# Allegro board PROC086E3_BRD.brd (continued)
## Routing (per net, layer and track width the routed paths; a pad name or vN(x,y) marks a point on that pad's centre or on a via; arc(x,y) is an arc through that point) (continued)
OV_VIN_DATA1: length 66.5
  TOP w0.178: v1(57.54,175.21) 57.34,175.01 U6.35
  L03_SIG1 w0.107: J3.25 9.2,192.43 9.2,190.57 10.44,189.34 11.53,189.34 13.51,187.36 31.65,187.36 32.49,186.52 32.49,185.76 32.58,185.67 33.23,185.67 33.32,185.58 33.32,185.44 33.23,185.35 32.58,185.35 32.49,185.26 32.49,177.38 33.96,175.9 56.85,175.9 v1(57.54,175.21)
OV_VIN_DATA2: length 66.6
  TOP w0.178: U6.33 58.14,175.62 v1(58.74,176.22)
  L03_SIG1 w0.107: J3.24 15.53,188.43 32.66,188.43 37.29,183.8 37.29,179 39.27,177.02 39.57,177.02 39.66,177.11 39.66,177.69 39.75,177.78 39.89,177.78 39.98,177.69 39.98,177.11 40.07,177.02 40.21,177.02 40.3,177.11 40.3,177.69 40.39,177.78 40.53,177.78 40.62,177.69 40.62,177.11 40.71,177.02 40.85,177.02 40.94,177.11 40.94,177.69 41.03,177.78 41.17,177.78 41.26,177.69 41.26,177.11 41.35,177.02 41.49,177.02 41.58,177.11 41.58,177.69 41.67,177.78 41.81,177.78 41.9,177.69 41.9,177.11 41.99,177.02 42.13,177.02 42.22,177.11 42.22,177.69 42.31,177.78 42.45,177.78 42.54,177.69 42.54,177.11 42.63,177.02 42.77,177.02 42.86,177.11 42.86,177.69 42.95,177.78 43.09,177.78 43.18,177.69 43.18,177.11 43.27,177.02 43.41,177.02 43.5,177.11 43.5,177.69 43.59,177.78 43.73,177.78 43.82,177.69 43.82,177.11 43.91,177.02 57.95,177.02 v1(58.74,176.22)
OV_VIN_DATA3: length 66.6
  TOP w0.178: v1(58.74,175.21) 58.54,175.01 U6.32
  L03_SIG1 w0.107: J3.23 11.74,192.43 11.74,190.42 14.07,188.1 32.49,188.1 35.2,185.38 35.2,177.07 35.59,176.69 36.16,176.69 36.26,176.78 36.26,177.21 36.35,177.3 36.48,177.3 36.58,177.21 36.58,176.78 36.67,176.69 36.8,176.69 36.9,176.78 36.9,177.21 36.99,177.3 37.12,177.3 37.22,177.21 37.22,176.78 37.31,176.69 37.44,176.69 37.54,176.78 37.54,177.21 37.63,177.3 37.76,177.3 37.86,177.21 37.86,176.78 37.95,176.69 57.84,176.69 58.22,176.31 58.22,175.73 v1(58.74,175.21)
OV_VIN_DATA4: length 66.5
  TOP w0.178: v1(59.94,176.22) 59.34,175.62 U6.30
  L03_SIG1 w0.107: J3.2 40.84,187.36 46.25,181.95 46.6,181.95 46.69,181.85 46.69,181.25 46.79,181.16 46.92,181.16 47.01,181.25 47.01,181.85 47.11,181.95 47.24,181.95 47.33,181.85 47.33,181.25 47.43,181.16 47.56,181.16 47.65,181.25 47.65,181.85 47.75,181.95 47.88,181.95 47.97,181.85 47.97,181.25 48.07,181.16 48.2,181.16 48.29,181.25 48.29,181.85 48.39,181.95 48.52,181.95 48.61,181.85 48.61,181.25 48.71,181.16 48.84,181.16 48.93,181.25 48.93,181.85 49.03,181.95 49.16,181.95 49.25,181.85 49.25,181.25 49.35,181.16 49.48,181.16 49.57,181.25 49.57,181.85 49.67,181.95 49.8,181.95 49.89,181.85 49.89,181.25 49.99,181.16 50.12,181.16 50.21,181.25 50.21,181.85 50.31,181.95 50.44,181.95 50.53,181.85 50.53,181.25 50.63,181.16 50.76,181.16 50.85,181.25 50.85,181.85 50.95,181.95 51.08,181.95 51.17,181.85 51.17,181.25 51.27,181.16 51.4,181.16 51.49,181.25 51.49,181.85 51.59,181.95 52.36,181.95 52.45,181.85 52.45,181.25 52.55,181.16 52.68,181.16 52.77,181.25 52.77,181.85 52.87,181.95 53,181.95 53.09,181.85 53.09,181.25 53.19,181.16 53.32,181.16 53.41,181.25 53.41,181.85 53.51,181.95 53.64,181.95 53.73,181.85 53.73,181.25 53.83,181.16 53.96,181.16 54.05,181.25 54.05,181.85 54.15,181.95 54.28,181.95 54.37,181.85 54.37,181.25 54.47,181.16 54.6,181.16 54.69,181.25 54.69,181.85 54.79,181.95 54.92,181.95 55.01,181.85 55.01,181.25 55.11,181.16 55.24,181.16 55.33,181.25 55.33,181.85 55.43,181.95 55.56,181.95 55.65,181.85 55.65,181.25 55.75,181.16 55.88,181.16 55.97,181.25 55.97,181.85 56.07,181.95 56.2,181.95 56.29,181.85 56.29,181.25 56.39,181.16 56.52,181.16 56.61,181.25 56.61,181.85 56.71,181.95 56.84,181.95 56.93,181.85 56.93,181.25 57.03,181.16 57.16,181.16 57.25,181.25 57.25,181.85 57.35,181.95 57.48,181.95 57.57,181.85 57.57,181.25 57.67,181.16 57.8,181.16 57.89,181.25 57.89,181.85 57.99,181.95 58.12,181.95 58.21,181.85 58.21,181.25 58.31,181.16 58.44,181.16 58.53,181.25 58.53,181.85 58.63,181.95 58.76,181.95 58.85,181.85 58.85,181.25 58.95,181.16 59.08,181.16 59.17,181.25 59.17,181.85 59.27,181.95 59.4,181.95 59.49,181.85 59.49,181.25 59.59,181.16 59.72,181.16 59.81,181.25 59.81,181.85 59.91,181.95 60.04,181.95 60.13,181.85 60.13,181.25 60.23,181.16 60.36,181.16 60.45,181.25 60.45,181.85 60.55,181.95 60.83,181.95 61.06,181.72 61.06,181.5 61.16,181.41 61.4,181.41 61.49,181.31 61.49,181.18 61.4,181.09 61.16,181.09 61.06,180.99 61.06,180.86 61.16,180.77 61.4,180.77 61.49,180.67 61.49,180.54 61.4,180.45 61.16,180.45 61.06,180.35 61.06,178.6 61.6,178.05 61.6,176.03 61.33,175.76 60.4,175.76 v1(59.94,176.22)
OV_VIN_DATA5: length 66.5
  TOP w0.178: U6.29 59.74,175.01 v1(59.94,175.21)
  L03_SIG1 w0.107: v1(59.94,175.21) 61.64,175.21 62.08,175.65 62.08,182 61.72,182.35 60.42,182.35 60.32,182.45 60.32,183.02 60.23,183.12 60.1,183.12 60,183.02 60,182.45 59.91,182.35 59.78,182.35 59.68,182.45 59.68,183.02 59.59,183.12 59.46,183.12 59.36,183.02 59.36,182.45 59.27,182.35 59.14,182.35 59.04,182.45 59.04,183.02 58.95,183.12 58.81,183.12 58.72,183.02 58.72,182.45 58.63,182.35 58.49,182.35 58.4,182.45 58.4,183.02 58.31,183.12 58.17,183.12 58.08,183.02 58.08,182.45 57.99,182.35 57.85,182.35 57.76,182.45 57.76,183.02 57.67,183.12 57.53,183.12 57.44,183.02 57.44,182.45 57.35,182.35 57.21,182.35 57.12,182.45 57.12,183.02 57.03,183.12 56.89,183.12 56.8,183.02 56.8,182.45 56.71,182.35 56.57,182.35 56.48,182.45 56.48,183.02 56.39,183.12 56.25,183.12 56.16,183.02 56.16,182.45 56.07,182.35 55.93,182.35 55.84,182.45 55.84,183.02 55.75,183.12 55.61,183.12 55.52,183.02 55.52,182.45 55.43,182.35 55.29,182.35 55.2,182.45 55.2,183.02 55.11,183.12 54.97,183.12 54.88,183.02 54.88,182.45 54.79,182.35 54.65,182.35 54.56,182.45 54.56,183.02 54.47,183.12 54.33,183.12 54.24,183.02 54.24,182.45 54.15,182.35 54.01,182.35 53.92,182.45 53.92,183.02 53.83,183.12 53.69,183.12 53.6,183.02 53.6,182.45 53.51,182.35 53.37,182.35 53.28,182.45 53.28,183.02 53.19,183.12 53.05,183.12 52.96,183.02 52.96,182.45 52.87,182.35 52.73,182.35 52.64,182.45 52.64,183.02 52.55,183.12 52.41,183.12 52.32,183.02 52.32,182.45 52.23,182.35 52.09,182.35 52,182.45 52,183.02 51.91,183.12 51.77,183.12 51.68,183.02 51.68,182.45 51.59,182.35 51.45,182.35 51.36,182.45 51.36,183.02 51.27,183.12 51.13,183.12 51.04,183.02 51.04,182.45 50.95,182.35 50.81,182.35 50.72,182.45 50.72,183.02 50.63,183.12 50.49,183.12 50.4,183.02 50.4,182.45 50.31,182.35 50.17,182.35 50.08,182.45 50.08,183.02 49.99,183.12 49.85,183.12 49.76,183.02 49.76,182.45 49.67,182.35 49.53,182.35 49.44,182.45 49.44,183.02 49.35,183.12 49.21,183.12 49.12,183.02 49.12,182.45 49.03,182.35 48.81,182.35 48.71,182.45 48.71,182.95 48.62,183.04 48.49,183.04 48.39,182.95 48.39,182.45 48.3,182.35 48.17,182.35 48.07,182.45 48.07,182.95 47.98,183.04 47.85,183.04 47.75,182.95 47.75,182.45 47.66,182.35 47.53,182.35 47.43,182.45 47.43,182.95 47.34,183.04 47.21,183.04 47.11,182.95 47.11,182.45 47.02,182.35 46.3,182.35 43.59,185.07 43.59,190.85 J3.1
OV_VIN_DATA6: length 66.5
  TOP w0.178: v1(61.14,176.22) 60.54,175.62 U6.27
  L03_SIG1 w0.107: v1(61.14,176.22) 60.1,177.27 60.1,180.62 59.99,180.73 59.59,180.73 59.48,180.62 59.48,179.88 59.39,179.79 59.26,179.79 59.16,179.88 59.16,180.64 59.07,180.73 58.94,180.73 58.84,180.64 58.84,179.88 58.75,179.79 58.62,179.79 58.52,179.88 58.52,180.64 58.43,180.73 58.3,180.73 58.2,180.64 58.2,179.88 58.11,179.79 57.98,179.79 57.88,179.88 57.88,180.64 57.79,180.73 56.54,180.73 56.44,180.64 56.44,179.1 56.35,179 56.22,179 56.12,179.1 56.12,180.64 56.03,180.73 53.9,180.73 53.81,180.64 53.81,179.17 53.71,179.08 53.58,179.08 53.49,179.17 53.49,180.64 53.39,180.73 53.26,180.73 53.17,180.64 53.17,179.17 53.07,179.08 52.94,179.08 52.85,179.17 52.85,180.64 52.75,180.73 52.62,180.73 52.53,180.64 52.53,179.17 52.43,179.08 52.3,179.08 52.21,179.17 52.21,180.64 52.11,180.73 51.98,180.73 51.89,180.64 51.89,179.17 51.79,179.08 51.66,179.08 51.57,179.17 51.57,180.64 51.47,180.73 51.34,180.73 51.25,180.64 51.25,179.17 51.15,179.08 51.02,179.08 50.93,179.17 50.93,180.64 50.83,180.73 50.7,180.73 50.61,180.64 50.61,179.17 50.51,179.08 50.38,179.08 50.29,179.17 50.29,180.64 50.19,180.73 48.96,180.73 48.86,180.64 48.86,180.27 48.77,180.17 48.64,180.17 48.54,180.27 48.54,180.64 48.45,180.73 48.32,180.73 48.22,180.64 48.22,180.27 48.13,180.17 48,180.17 47.9,180.27 47.9,180.64 47.81,180.73 47.68,180.73 47.58,180.64 47.58,180.27 47.49,180.17 47.36,180.17 47.26,180.27 47.26,180.64 47.17,180.73 47.04,180.73 46.94,180.64 46.94,180.27 46.85,180.17 46.72,180.17 46.62,180.27 46.62,180.64 46.53,180.73 46.4,180.73 46.3,180.64 46.3,180.27 46.21,180.17 46.08,180.17 45.98,180.27 45.98,180.64 45.89,180.73 45.67,180.73 45.42,180.98 45.42,182.34 38.3,189.45 J3.4
OV_VIN_DATA7: length 66.5
  TOP w0.178: U6.26 v1(60.94,172.69)
  L03_SIG1 w0.107: v1(60.94,172.69) 59.28,174.35 59.28,176.33 58.27,177.35 46.2,177.35 44.37,179.18 43.54,179.18 43.44,179.27 43.44,180.66 43.35,180.75 43.22,180.75 43.12,180.66 43.12,179.27 43.03,179.18 42.9,179.18 42.8,179.27 42.8,180.66 42.71,180.75 42.58,180.75 42.48,180.66 42.48,179.27 42.39,179.18 42.26,179.18 42.16,179.27 42.16,180.66 42.07,180.75 41.94,180.75 41.84,180.66 41.84,179.27 41.75,179.18 41.62,179.18 41.52,179.27 41.52,180.66 41.43,180.75 41.3,180.75 41.2,180.66 41.2,179.27 41.11,179.18 40.98,179.18 40.88,179.27 40.88,180.66 40.79,180.75 40.66,180.75 40.56,180.66 40.56,179.27 40.47,179.18 40.34,179.18 40.24,179.27 40.24,180.66 40.15,180.75 40.02,180.75 39.92,180.66 39.92,179.27 39.83,179.18 39.7,179.18 39.6,179.27 39.6,180.66 39.51,180.75 39.38,180.75 39.28,180.66 39.28,179.27 39.19,179.18 39.06,179.18 38.96,179.27 38.96,180.66 38.87,180.75 38.74,180.75 38.64,180.66 38.64,179.27 38.55,179.18 38.25,179.18 37.85,179.59 37.85,184.03 37.14,184.73 37.14,192.3 38.3,193.45 J3.3
OV_VIN_DATA8: length 66.5
  TOP w0.178: J3.6 35.76,189.85 35.53,189.62 32.31,189.62 32.13,189.44 32.13,188.6 32.36,188.37 32.68,188.37 32.83,188.53 32.83,188.9 32.99,189.06 33.21,189.06 33.37,188.9 33.37,188.53 33.52,188.37 33.74,188.37 33.9,188.53 33.9,188.9 34.06,189.06 34.28,189.06 34.43,188.9 34.43,188.53 34.59,188.37 34.81,188.37 34.97,188.53 34.97,188.9 35.12,189.06 35.34,189.06 35.5,188.9 35.5,188.53 35.66,188.37 35.88,188.37 36.03,188.53 36.03,188.9 36.19,189.06 36.41,189.06 36.57,188.9 36.57,188.53 36.72,188.37 36.94,188.37 37.1,188.53 37.1,188.9 37.26,189.06 37.48,189.06 37.63,188.9 37.63,188.53 37.79,188.37 38.01,188.37 38.17,188.53 38.17,188.9 38.32,189.06 38.54,189.06 38.7,188.9 38.7,188.53 38.86,188.37 39.08,188.37 39.23,188.53 39.23,188.9 39.39,189.06 39.61,189.06 39.77,188.9 39.77,188.53 39.92,188.37 40.14,188.37 40.3,188.53 40.3,188.9 40.46,189.06 40.68,189.06 40.83,188.9 40.83,188.53 40.99,188.37 41.59,188.37 41.75,188.53 41.75,188.9 41.9,189.06 42.75,189.06 43.28,188.53 55.55,188.53 57.21,186.86 58.61,186.86 58.76,186.71 58.76,186.35 58.92,186.19 59.14,186.19 59.3,186.35 59.3,186.71 59.45,186.86 59.68,186.86 59.83,186.71 59.83,186.35 59.99,186.19 60.21,186.19 60.36,186.35 60.36,186.71 60.52,186.86 66.23,186.86 66.6,186.5 66.6,183.96 66.78,183.78 68.26,183.78 68.61,183.43 68.61,175.67 68.25,175.32 U7.36
OV_VIN_DATA9: length 66.5
  TOP w0.178: U7.35 68.65,175.08 69.04,175.47 69.04,183.85 68.15,184.74 68.15,186.22 67.12,187.24 62.95,187.24 60.76,189.44 59.86,189.44 59.7,189.29 59.7,187.9 59.54,187.74 59.32,187.74 59.17,187.9 59.17,189.29 59.01,189.44 58.79,189.44 58.63,189.29 58.63,187.9 58.48,187.74 58.26,187.74 58.1,187.9 58.1,189.29 57.94,189.44 57.72,189.44 57.57,189.29 57.57,187.9 57.41,187.74 57.19,187.74 57.03,187.9 57.03,189.29 56.88,189.44 55.06,189.44 54.91,189.29 54.91,189.06 54.75,188.91 54.53,188.91 54.37,189.06 54.37,189.29 54.22,189.44 53.9,189.44 53.74,189.29 53.74,189.06 53.59,188.91 53.37,188.91 53.21,189.06 53.21,189.29 53.05,189.44 52.83,189.44 52.68,189.29 52.68,189.06 52.52,188.91 52.3,188.91 52.14,189.06 52.14,189.29 51.99,189.44 51.77,189.44 51.61,189.29 51.61,189.06 51.45,188.91 51.23,188.91 51.08,189.06 51.08,189.29 50.92,189.44 50.7,189.44 50.54,189.29 50.54,189.06 50.39,188.91 50.17,188.91 50.01,189.06 50.01,189.29 49.85,189.44 49.63,189.44 49.48,189.29 49.48,189.06 49.32,188.91 49.1,188.91 48.94,189.06 48.94,189.29 48.79,189.44 48.57,189.44 48.41,189.29 48.41,189.06 48.25,188.91 48.03,188.91 47.88,189.06 47.88,189.29 47.72,189.44 47.5,189.44 47.34,189.29 47.34,189.06 47.19,188.91 46.97,188.91 46.81,189.06 46.81,189.29 46.65,189.44 46.43,189.44 46.28,189.29 46.28,189.06 46.12,188.91 45.9,188.91 45.74,189.06 45.74,189.29 45.59,189.44 45.37,189.44 45.21,189.29 45.21,189.06 45.05,188.91 44.83,188.91 44.68,189.06 44.68,189.29 44.52,189.44 44.3,189.44 44.14,189.29 44.14,189.06 43.99,188.91 43.77,188.91 43.61,189.06 43.61,189.29 43.45,189.44 37.62,189.44 37.06,190 37.06,192.3 J3.5
OV_VIN_DATA10: length 66.5
  TOP w0.178: U7.33 69.45,184.13 68.58,185 68.58,186.36 67.21,187.73 63.12,187.73 60.85,190 43.36,190 42.93,190.43 42.93,190.78 43.08,190.94 44.07,190.94 44.22,191.09 44.22,191.31 44.07,191.47 43.08,191.47 42.93,191.63 42.93,191.85 43.08,192 44.07,192 44.22,192.16 44.22,192.38 44.07,192.54 43.08,192.54 42.93,192.69 42.93,192.91 43.08,193.07 44.07,193.07 44.22,193.23 44.22,193.45 44.07,193.6 43.08,193.6 42.93,193.76 42.93,193.98 43.08,194.14 44.07,194.14 44.22,194.29 44.22,194.51 44.07,194.67 43.08,194.67 42.55,195.21 34.98,195.21 34.52,194.75 34.52,192.35 J3.8
OV_VIN_DATA11: length 66.6
  TOP w0.178: U7.32 69.85,185.66 67.25,188.26 63.22,188.26 60.95,190.53 50.95,190.53 50.79,190.69 50.79,191.27 50.64,191.42 50.42,191.42 50.26,191.27 50.26,190.69 50.1,190.53 49.88,190.53 49.73,190.69 49.73,191.27 49.57,191.42 49.35,191.42 49.19,191.27 49.19,190.69 49.04,190.53 48.82,190.53 48.66,190.69 48.66,191.27 48.5,191.42 48.28,191.42 48.13,191.27 48.13,190.69 47.97,190.53 47.54,190.53 47.39,190.69 47.39,191.09 47.23,191.24 47.01,191.24 46.85,191.09 46.85,190.69 46.7,190.53 46.23,190.53 46.05,190.71 46.05,190.8 45.89,190.95 45.34,190.95 45.19,191.11 45.19,191.33 45.34,191.49 45.89,191.49 46.05,191.64 46.05,191.86 45.89,192.02 45.34,192.02 45.19,192.18 45.19,192.4 45.34,192.55 45.89,192.55 46.05,192.71 46.05,192.93 45.89,193.09 45.34,193.09 45.19,193.24 45.19,193.46 45.34,193.62 45.89,193.62 46.05,193.78 46.05,195.44 45.69,195.79 33.96,195.79 33.22,195.05 J3.7
OV_VIN_HD: length 66.5
  TOP w0.178: U7.27 71.85,175.02 70.33,176.54 70.33,185.75 67.36,188.72 63.53,188.72 60.44,191.8 54.16,191.8 54.01,191.65 54.01,191.12 53.85,190.97 53.63,190.97 53.47,191.12 53.47,191.65 53.32,191.8 53.1,191.8 52.94,191.65 52.94,191.12 52.78,190.97 52.56,190.97 52.41,191.12 52.41,191.65 52.25,191.8 52.03,191.8 51.87,191.65 51.87,191.12 51.72,190.97 51.5,190.97 51.34,191.12 51.34,191.65 51.18,191.8 v1(47.09,191.8)
  BOTTOM w0.178: J3.13 25.6,194.65 26.21,195.26 41.86,195.26 45.31,191.8 TP16.1 v1(47.09,191.8)
OV_VIN_PCLK: length 60.5
  TOP w0.178: U5.6 48.12,174.9 v1(47.93,175.09)
  BOTTOM w0.178: R312.1 22.7,187.89 TP17.1 33.32,187.89 35.41,185.8 35.41,178.6 35.25,178.45 34.75,178.45 34.59,178.29 34.59,178.07 34.75,177.91 35.25,177.91 35.41,177.76 35.41,177.53 35.25,177.38 34.75,177.38 34.59,177.22 34.59,177 34.75,176.85 35.25,176.85 35.41,176.69 35.41,175.73 35.59,175.55 35.96,175.55 36.12,175.7 36.12,176.59 36.28,176.74 36.5,176.74 36.65,176.59 36.65,175.7 36.81,175.55 37.03,175.55 37.19,175.7 37.19,176.59 37.34,176.74 37.57,176.74 37.72,176.59 37.72,175.7 37.88,175.55 38.1,175.55 38.25,175.7 38.25,176.59 38.41,176.74 38.63,176.74 38.79,176.59 38.79,175.7 38.94,175.55 39.17,175.55 39.32,175.7 39.32,176.59 39.48,176.74 39.7,176.74 39.85,176.59 39.85,175.7 40.01,175.55 40.23,175.55 40.39,175.7 40.39,176.59 40.54,176.74 40.77,176.74 40.92,176.59 40.92,175.7 41.08,175.55 41.3,175.55 41.46,175.7 41.46,176.59 41.61,176.74 41.83,176.74 41.99,176.59 41.99,175.7 42.14,175.55 42.37,175.55 42.52,175.7 42.52,176.59 42.68,176.74 42.9,176.74 43.06,176.59 43.06,175.7 43.21,175.55 43.43,175.55 43.59,175.7 43.59,176.59 43.74,176.74 43.97,176.74 44.12,176.59 44.12,175.7 44.28,175.55 44.5,175.55 44.66,175.7 44.66,176.59 44.81,176.74 45.03,176.74 45.19,176.59 45.19,175.7 45.35,175.55 45.57,175.55 45.72,175.7 45.72,176.59 45.88,176.74 46.1,176.74 46.26,176.59 46.26,175.7 46.41,175.55 47.47,175.55 v1(47.93,175.09)
OV_VIN_PCLK_R: length 6.2
  BOTTOM w0.178: R312.2 21.84,192.27 J3.17
OV_VIN_VD: length 66.6
  TOP w0.178: v1(47.09,193.92) 48.6,192.41 60.46,192.41 63.76,189.12 67.6,189.12 70.71,186 70.71,176.92 72.25,175.39 U7.26
  BOTTOM w0.178: v1(47.09,193.92) TP15.1 44.54,193.92 42.34,196.12 24.13,196.12 23.06,195.05 J3.15
PCLK_R: length 2.9
  TOP w0.178: U8.10 28.44,165.86 28.27,166.03 R27.2 R26.2
PERIPH_RSTZ: length 70.5
  TOP w0.178: R146.2 v1(94.51,112.52) ; v1(94.71,50.99) 94.07,51.63 J2.28
  L03_SIG1 w0.107: v1(94.71,50.99) 94.17,51.53 94.17,57.15 98.74,61.72 98.74,73.12 96.34,75.52 96.34,110.69 v1(94.51,112.52)
PWR_SW_UB921: length 72.1
  TOP w0.178: v1(65.43,161.12) 64.72,160.41 55.24,160.41 46.58,151.75 32.97,151.75 32.21,150.99 28.5,150.99 27.38,152.1 23.16,152.1 21.13,154.14 15.6,154.14 15.24,153.78 15.24,151.6 14.32,150.68 v1(13.47,150.68) R71.1
  L08_SIG2 w0.107: v1(65.43,161.12) 65.49,161.06 68.73,161.06 70.74,159.05 v1(70.74,157.46)
  BOTTOM w0.178: U43.14 70.31,156.91 70.74,157.35 v1(70.74,157.46) ; U44.3 v1(13.47,150.68)
PWR_SW_UB926: length 79.4
  TOP w0.178: U15.5 v1(59.28,133.67)
  L03_SIG1 w0.107: v1(12.73,169.58) 12.88,169.73 14.63,169.73 15.7,168.66 15.7,167.14 18.95,163.89 18.95,158.71 21.2,156.46 21.2,155.69 22.2,154.69 22.2,147.99 24.28,145.91 24.28,135.9 25.18,135 42.56,135 44.55,133 58.61,133 v1(59.28,133.67)
  BOTTOM w0.178: U40.3 R331.1 v1(12.73,169.58)
R_CDCE_Y1: length 2.6
  TOP w0.178: v1(39.93,153.14) 39.82,153.26 R63.2
  BOTTOM w0.178: v1(39.93,153.14) 39.82,153.26 U42.11
R_CODEC1_ACLKX: length 1.3
  BOTTOM w0.178: R188.1 U21.6
R_CODEC1_SCKI: length 1.4
  BOTTOM w0.178: R215.1 63.83,67.1 U25.6
R_CODEC2_ACLKX: length 1.3
  BOTTOM w0.178: R187.1 U21.3
R_CODEC2_SCKI: length 1.4
  BOTTOM w0.178: R214.1 63.83,72.61 U25.3
R_DIR_XTO: length 4.7
  BOTTOM w0.178: Y1.2 C267.1 R359.2
R_LI_VIN_PCLK: length 1.7
  BOTTOM w0.178: R324.2 J6.9
R_OV_CAM_PWDN: length 14.7
  BOTTOM w0.178: J3.10 30.68,189.24 31.39,188.53 R311.1 R313.2 R318.1
REFCLK0: length 64.5
  L03_SIG1 w0.107: v1(92.57,102.51) 91.3,101.24 91.3,89.84 75.11,73.65 v1(75.11,71.5)
  BOTTOM w0.178: R537.2 91.17,103.91 v1(92.57,102.51) ; v1(75.11,71.5) 66.19,71.5 65.53,70.84 R539.1
REFCLK0/MCASP6_AFSR: length 5.5
  TOP w0.178: J1.86 v1(92.41,120.51)
  BOTTOM w0.178: R537.1 89.69,118.97 90.25,119.54 91.44,119.54 v1(92.41,120.51)
REFCLK0/REFCLK2: length 7.5
  BOTTOM w0.178: U25.2 63.33,70.32 64.33,69.32 U25.5 TP9.1 66.37,68.73 R539.2
RESETSTATZ: length 3.8
  TOP w0.178: J2.30 TP10.1
RXIN_OPTICAL: length 20.4
  TOP w0.178: MOD1.3 10.76,144.99 11.35,144.39 SW1.3
SOC_I2C2_SCL: length 2.8
  TOP w0.178: J1.112 v1(93.04,127.01)
  BOTTOM w0.178: TP53.1 93.57,126.47 v1(93.04,127.01)
SOC_I2C2_SDA: length 2.9
  TOP w0.178: J1.114 92.68,127.51 v1(93.01,127.85)
  BOTTOM w0.178: v1(93.01,127.85) 93.55,128.38 TP52.1
SOC_PORZ_OUT: length 1.8
  TOP w0.178: J1.64 R144.2
SPI3_CLK: length 36.7
  TOP w0.178: v1(66.88,142.48) 66.21,141.81 U10.23 ; J1.105 v1(84.03,125.51)
  L08_SIG2 w0.107: v1(84.03,125.51) 84.25,125.73 84.25,139.71 80.59,143.37 67.77,143.37 v1(66.88,142.48)
SPI3_CLK_MUX: length 39.7
  TOP w0.178: U10.33 66.71,150.57 66.22,151.06 v1(66.22,152.59) ; U4.10 v1(42.9,169.15)
  L03_SIG1 w0.107: v1(66.22,152.59) 66.22,153.6 64.06,155.76 62.54,155.76 56.04,162.26 49.94,162.26 46.84,165.36 46.84,169.75 46.73,169.86 43.61,169.86 v1(42.9,169.15)
SPI3_CS0: length 95.8
  TOP w0.178: v1(93.44,109.01) 92.94,108.51 J1.58 ; U4.11 v1(43.3,166.89)
  L08_SIG2 w0.107: v1(43.3,166.89) 43.3,162.52 44.45,161.37 48.26,161.37 65.56,144.08 83.82,144.08 85.39,142.5 85.39,135.09 90.22,130.26 90.22,127.49 92.99,124.72 92.99,122.64 94.31,121.32 94.31,113.85 93.44,112.98 v1(93.44,109.01)
SPI3_D0: length 36.7
  TOP w0.178: v1(67.46,136.13) 66.88,136.71 66.88,139.15 67.21,139.48 U10.25 ; J1.101 v1(84.03,124.51)
  L03_SIG1 w0.107: v1(84.03,124.51) 83.46,123.93 82.47,123.93 81.51,124.9 81.51,127.54 83.92,129.95 83.92,132.65 81.33,135.24 74.07,135.24 73.36,134.53 68.63,134.53 67.46,135.7 v1(67.46,136.13)
SPI3_D1: length 47.6
  TOP w0.178: U10.11 60.21,138.83 60.63,138.41 63.07,138.41 63.35,138.13 v1(63.45,138.13) ; J1.103 83.75,125.01 83.21,124.47 v1(82.98,124.47)
  L03_SIG1 w0.107: v1(63.45,138.13) 66.47,138.13 67.98,136.62 67.98,135.73 68.83,134.88 73.2,134.88 73.91,135.59 83.72,135.59 88.29,131.02 88.29,127.36 87.68,126.75 83.97,126.75 83.41,126.2 83.41,124.9 v1(82.98,124.47)
SPI3_MISO: length 33
  TOP w0.178: v1(61.01,151.19) 61.01,150.99 61.21,150.78 U10.44 ; U5.12 48.52,166.89 v1(48.16,166.53)
  L03_SIG1 w0.107: v1(63.88,156.22) 63.4,156.7 62.07,156.7 56.05,162.72 51.28,162.72 48.16,165.84 v1(48.16,166.53)
  BOTTOM w0.178: v1(63.88,156.22) 63.4,156.7 63.02,156.7 60.45,154.14 60.45,151.75 v1(61.01,151.19)
SPI3_MOSI: length 38.5
  TOP w0.178: U10.31 67.71,149.24 v1(67.26,149.69) ; U4.12 v1(43.7,169.15)
  L03_SIG1 w0.107: v1(67.26,149.69) 65.71,151.24 65.71,153.6 63.91,155.41 62.43,155.41 55.93,161.91 49.85,161.91 46.51,165.25 46.51,169.4 46.4,169.5 44.05,169.5 v1(43.7,169.15)
U37_CL: length 1.8
  BOTTOM w0.178: R332.1 21.97,168.67 21.71,168.93 U40.13
U37_DIAG_EN: length 1.8
  BOTTOM w0.178: U40.12 21.74,169.58 22,169.84 R330.1
U66_CL: length 1.8
  BOTTOM w0.178: U44.13 21.17,150.03 21.48,149.72 R353.1
U66_DIAG_EN: length 1.8
  BOTTOM w0.178: R349.1 21.44,150.99 21.13,150.68 U44.12
UB921_DIN0: length 80.5
  TOP w0.178: v1(70.46,146.11) 71.78,144.79 U11.3 ; v1(35.76,162.2) 35.26,161.7 U8.43
  L03_SIG1 w0.107: v1(35.76,162.2) 36.08,162.2 36.37,161.91 42.85,161.91 43.66,161.1 45.82,161.1 48.07,158.85 55.62,158.85 58.39,156.08 58.39,153.89 56.95,152.45 56.95,152.11 57.75,151.32 59.08,151.32 59.18,151.42 59.18,151.69 59.08,151.8 58.93,151.8 58.57,152.16 58.57,152.81 58.72,152.97 59.44,152.97 60.5,151.9 60.5,150.33 60.17,150 60.17,149.79 60.27,149.69 62,149.69 62.09,149.6 62.09,147.92 62,147.83 61.87,147.83 61.77,147.92 61.77,149.28 61.68,149.37 61.55,149.37 61.45,149.28 61.45,147.92 61.36,147.83 61.23,147.83 61.13,147.92 61.13,149.28 61.04,149.37 60.91,149.37 60.81,149.28 60.81,147.92 60.72,147.83 60.59,147.83 60.49,147.92 60.49,149.28 60.4,149.37 60.27,149.37 60.17,149.28 60.17,147.61 60.4,147.38 61.63,147.38 61.73,147.27 61.73,146.84 62.66,145.91 62.88,145.91 62.98,146 62.98,147.74 63.07,147.83 63.86,147.83 63.96,147.74 63.96,147.61 63.86,147.51 63.39,147.51 63.3,147.42 63.3,147.28 63.39,147.19 63.86,147.19 63.96,147.1 63.96,146.96 63.86,146.87 63.39,146.87 63.3,146.78 63.3,146.64 63.39,146.55 63.86,146.55 63.96,146.46 63.96,146.32 63.86,146.23 63.39,146.23 63.3,146.14 63.3,146 63.39,145.91 64.29,145.91 65.1,146.72 68.17,146.72 68.98,145.91 70.26,145.91 v1(70.46,146.11)
UB921_DIN1: length 80.5
  TOP w0.178: U8.44 v1(34.49,162.2) ; v1(71.42,146.11) 72.78,144.76 U11.5
  L03_SIG1 w0.107: v1(71.42,146.11) 70.92,145.6 62.53,145.6 61.67,146.46 61.52,146.46 61.42,146.56 61.42,146.93 61.33,147.02 61.12,147.02 61.01,146.92 61.01,146.56 60.92,146.47 60.78,146.47 59.25,148 57.44,148 57.3,148.14 57.3,150.59 57.4,150.69 57.53,150.69 57.62,150.59 57.62,148.46 57.72,148.36 57.85,148.36 57.94,148.46 57.94,150.59 58.04,150.69 58.17,150.69 58.26,150.59 58.26,148.46 58.36,148.36 58.49,148.36 58.58,148.46 58.58,150.59 58.68,150.69 58.81,150.69 58.9,150.59 58.9,148.46 59,148.36 59.13,148.36 59.22,148.46 59.22,150.59 59.32,150.69 59.45,150.69 59.54,150.59 59.54,148.46 59.64,148.36 59.77,148.36 59.86,148.46 59.86,150.91 59.77,151.01 57.48,151.01 57.3,151.19 57.3,151.32 56.64,151.98 56.64,152.58 57.97,153.91 57.97,156.02 55.45,158.54 47.92,158.54 45.69,160.76 37.06,160.76 36.12,161.7 34.99,161.7 v1(34.49,162.2)
UB921_DIN2: length 80.4
  TOP w0.178: U11.7 73.78,145.99 v1(73.71,146.11) ; U8.45 35.26,162.7 v1(35.76,163.2)
  L03_SIG1 w0.107: v1(35.76,163.2) 36.05,163.2 36.58,162.67 38.49,162.67 39.4,163.58 40.61,163.58 40.7,163.68 40.7,164.13 40.79,164.22 42.02,164.22 42.11,164.13 42.11,164 42.02,163.9 41.11,163.9 41.02,163.81 41.02,163.68 41.11,163.58 43.21,163.58 43.31,163.69 43.31,164.05 43.42,164.16 43.63,164.16 43.74,164.05 43.74,163.69 43.86,163.57 45.34,163.57 45.61,163.31 45.61,162.63 48.33,159.91 48.46,159.91 48.56,160 48.56,160.14 46.06,162.63 46.06,162.77 46.15,162.86 46.29,162.86 49.02,160.13 55.27,160.13 59.49,155.91 59.49,154.95 59.13,154.59 59.13,154.24 59.31,154.06 59.44,154.06 60.22,154.83 60.35,154.83 61.21,153.97 61.21,153.84 61.11,153.75 60.98,153.75 60.35,154.38 60.22,154.38 60.12,154.28 60.12,154.15 60.75,153.52 60.75,153.39 60.66,153.29 60.53,153.29 59.9,153.92 59.76,153.92 59.67,153.83 59.67,153.7 60.99,152.38 61.12,152.38 61.44,152.7 61.57,152.7 62.21,152.07 62.21,151.93 62.11,151.84 61.98,151.84 61.57,152.25 61.44,152.25 61.35,152.16 61.35,152.02 62.84,150.53 62.84,149.77 63.5,149.11 64.11,149.11 64.62,148.6 64.62,147.54 64.72,147.43 68.94,147.43 69.04,147.34 69.04,146.99 69.13,146.89 69.26,146.89 69.36,146.99 69.36,147.34 69.45,147.43 69.58,147.43 69.68,147.34 69.68,146.99 69.77,146.89 69.9,146.89 70,146.99 70,147.34 70.09,147.43 70.23,147.43 70.32,147.34 70.32,146.99 70.41,146.89 70.55,146.89 70.64,146.99 70.64,147.34 70.73,147.43 71.42,147.43 71.63,147.63 73.17,147.63 73.28,147.53 73.28,146.24 73.41,146.11 v1(73.71,146.11)
UB921_DIN3: length 80.3
  TOP w0.178: U8.46 v1(34.49,163.2) ; U11.10 75.28,145.2 v1(74.63,145.86)
  L03_SIG1 w0.107: v1(74.63,145.86) 74.37,145.6 72.29,145.6 72.09,145.8 72.09,146.13 71.64,146.58 68.82,146.58 68.37,147.03 64.37,147.03 64.27,147.14 64.27,147.87 63.99,148.14 63.32,148.14 63.22,148.23 63.22,148.37 63.32,148.46 63.83,148.46 63.93,148.55 63.93,148.69 63.83,148.78 63,148.78 62.9,148.69 62.9,148.23 62.81,148.14 62.51,148.14 62.4,148.25 62.4,149.73 62.13,150 61.88,150 61.77,150.11 61.77,151.09 58.72,154.14 58.72,154.84 58.83,154.95 59.02,154.95 59.13,155.06 59.13,155.5 59.04,155.6 58.82,155.6 58.72,155.69 58.72,156.22 55.78,159.16 55.47,159.16 55.47,159.16 49.32,159.16 49.23,159.25 49.23,159.39 49.32,159.48 55.02,159.48 55.12,159.57 55.12,159.71 55.02,159.8 49,159.8 48.91,159.71 48.91,159.25 48.82,159.16 48.27,159.16 45.97,161.45 43.84,161.45 43,162.29 39.79,162.29 39.7,162.38 39.7,162.52 39.79,162.61 42.91,162.61 43,162.7 43,162.84 42.91,162.93 39.47,162.93 39.38,162.84 39.38,162.38 39.28,162.29 36.47,162.29 36.07,162.7 35,162.7 v1(34.49,163.2)
UB921_DIN4: length 80.3
  TOP w0.178: v1(76.76,146.49) 76.28,146 U11.12 ; v1(35.76,164.2) 35.26,163.7 U8.47
  L03_SIG1 w0.107: v1(35.76,164.2) 36.11,164.2 36.88,163.43 37.28,163.43 37.49,163.64 37.49,164.55 36.89,165.15 36.89,168.71 37.04,168.87 37.79,168.87 37.95,168.71 37.95,166.3 38.13,166.12 38.35,166.12 38.45,166.03 38.45,165.57 38.54,165.48 38.88,165.48 38.98,165.59 38.98,165.9 39.09,166.01 39.3,166.01 39.41,165.9 39.41,165.59 39.52,165.48 39.73,165.48 39.84,165.59 39.84,165.9 39.94,166.01 40.16,166.01 40.26,165.9 40.26,165.59 40.37,165.48 40.58,165.48 40.69,165.59 40.69,165.9 40.8,166.01 41.01,166.01 41.12,165.9 41.12,165.59 41.22,165.48 41.65,165.48 42.18,166.02 44.25,166.02 49.38,160.89 55.53,160.89 64.67,151.75 64.67,149.51 66.04,148.14 71.17,148.14 71.32,148.29 78.84,148.29 79.4,147.73 81.02,147.73 81.13,147.63 81.13,146.59 81.02,146.49 v1(76.76,146.49)
UB921_DIN5: length 80.4
  TOP w0.178: v1(76.8,145.75) 76.91,145.75 77.28,145.39 U11.14 ; U8.48 v1(34.49,164.2)
  L03_SIG1 w0.107: v1(34.49,164.2) 34.49,164.95 34.6,165.06 35.74,165.06 36.02,165.34 36.02,168.96 36.13,169.07 36.47,169.07 36.58,168.96 36.58,164.81 36.47,164.7 35.41,164.7 35.2,164.5 35.2,164.07 35.57,163.7 36,163.7 36.65,163.05 38.43,163.05 38.81,163.43 38.81,164.55 38.64,164.72 37.9,164.72 37.8,164.83 37.8,165.06 37.9,165.17 40.81,165.17 41.27,164.71 42.89,164.71 43,164.82 43,165 43.1,165.11 43.32,165.11 43.42,165 43.42,164.82 43.53,164.71 44.98,164.71 49.21,160.49 55.42,160.49 61.75,154.16 61.75,152.99 61.93,152.81 63.09,152.81 63.35,152.56 63.35,151.49 63.55,151.29 64.25,151.29 64.36,151.18 64.36,149.31 65.89,147.79 71.32,147.79 71.52,147.98 78.18,147.98 78.28,147.88 78.28,147.63 78.18,147.52 76.85,147.52 76.23,146.9 76.23,146.33 v1(76.8,145.75)
UB921_DIN6: length 80.5
  TOP w0.178: v1(34.67,165.87) 33.25,165.87 32.94,165.57 U8.1 ; U11.16 v1(78.28,142.8)
  L03_SIG1 w0.107: v1(34.67,165.87) 34.75,165.87 35.2,166.33 35.2,167.34 35.31,167.45 35.61,167.45 35.71,167.34 35.71,165.52 35.57,165.38 34.26,165.38 34.01,165.13 34.01,158.89 34.52,158.38 44.68,158.38 46.69,156.37 53.24,156.37 54.2,155.41 54.2,153.27 53.89,152.96 51.74,152.96 51.53,153.17 49.56,153.17 49.38,152.99 49.38,151.77 51.04,150.12 51.59,150.12 53.59,148.12 53.59,146.53 54.79,145.33 56.64,145.33 58.68,143.29 75.26,143.29 75.75,142.8 v1(78.28,142.8)
UB921_DIN7: length 80.5
  TOP w0.178: v1(34.62,166.76) 33.35,166.76 32.44,165.85 U8.2 ; U11.20 v1(80.28,142.8)
  L03_SIG1 w0.107: v1(34.62,166.76) 33.68,165.82 33.68,158.66 34.29,158.05 44.53,158.05 46.53,156.04 53.09,156.04 53.85,155.28 53.85,153.53 53.59,153.27 51.87,153.27 51.51,153.63 49.33,153.63 49.02,153.32 49.02,151.69 50.95,149.77 51.51,149.77 53.24,148.04 53.24,146.45 54.66,145.02 56.51,145.02 58.57,142.96 74.98,142.96 75.62,142.32 79.8,142.32 v1(80.28,142.8)
UB921_DIN8: length 80.6
  TOP w0.178: U8.35 32.44,156.63 v1(32.94,156.13) ; U11.22 v1(81.28,141.79)
  L03_SIG1 w0.107: v1(81.28,141.79) 81.15,141.66 65.35,141.66 64.72,142.3 59.76,142.3 59.67,142.21 59.67,142.07 59.76,141.98 62.59,141.98 62.69,141.89 62.69,141.75 62.59,141.66 59.44,141.66 59.35,141.75 59.35,142.21 59.25,142.3 58.22,142.3 56.29,144.23 54.56,144.23 46.08,152.71 42.16,152.71 41.76,152.31 41.2,152.31 41.1,152.41 41.1,152.61 40.99,152.71 40.54,152.71 40.45,152.62 40.45,152.4 40.35,152.31 35.98,152.31 35.89,152.4 35.89,152.53 35.98,152.63 37.65,152.63 37.74,152.72 37.74,152.85 37.65,152.95 35.98,152.95 35.89,153.04 35.89,153.17 35.98,153.27 37.65,153.27 37.74,153.36 37.74,153.49 37.65,153.59 35.98,153.59 35.89,153.68 35.89,153.81 35.98,153.91 37.65,153.91 37.74,154 37.74,154.13 37.65,154.23 35.75,154.23 35.57,154.04 35.57,152.4 35.48,152.31 35.06,152.31 34.95,152.41 34.95,153.58 32.94,155.58 v1(32.94,156.13)
UB921_DIN9: length 80.4
  TOP w0.178: U11.24 v1(82.28,142.8) ; U8.36 32.94,156.88 33.3,156.52 34.62,156.52 35.31,155.84 v1(35.31,154.97)
  L03_SIG1 w0.107: v1(35.31,154.97) 34.73,154.97 34.62,154.87 34.62,154.5 34.73,154.39 35.46,154.39 35.76,154.69 37.8,154.69 38.05,154.44 38.05,153.74 38.16,153.63 38.47,153.63 38.57,153.73 38.57,155.55 38.67,155.66 39.67,155.66 39.83,155.5 39.83,155.35 39.73,155.25 38.99,155.25 38.9,155.16 38.9,155.03 38.99,154.93 39.69,154.93 39.8,154.82 39.8,154.69 39.71,154.59 39.01,154.59 38.92,154.5 38.92,154.37 39.01,154.27 39.71,154.27 39.8,154.18 39.8,154.05 39.71,153.95 39.01,153.95 38.92,153.86 38.92,153.73 39.01,153.63 40.09,153.63 40.7,153.02 40.98,153.02 41.07,153.12 41.07,153.57 41.18,153.68 45.81,153.68 45.92,153.57 45.92,153.44 45.83,153.34 41.49,153.34 41.39,153.25 41.39,153.12 41.49,153.02 46.22,153.02 54.53,144.71 56.34,144.71 58.42,142.63 65,142.63 65.63,141.99 80.42,141.99 81.23,142.8 v1(82.28,142.8)
UB921_DIN10: length 80.5
  TOP w0.178: U8.37 35.26,158.7 v1(35.76,159.2) ; U11.26 v1(83.28,142.8)
  L03_SIG1 w0.107: v1(35.76,159.2) 35.93,159.04 45.03,159.04 47.08,156.99 54.76,156.99 54.87,156.88 54.87,152.23 54.34,151.7 51.89,151.7 51.8,151.61 51.8,151.48 51.89,151.38 54.03,151.38 54.12,151.29 54.12,151.16 54.03,151.06 51.57,151.06 51.48,151.16 51.48,151.6 51.37,151.7 50.83,151.7 50.72,151.6 50.72,151.31 51.29,150.74 51.85,150.74 54.21,148.38 54.21,146.84 55.1,145.95 56.89,145.95 58.94,143.91 75.89,143.91 76.23,143.57 77.83,143.57 78.17,143.91 84.44,143.91 84.58,143.77 84.58,142.41 84.48,142.3 83.78,142.3 v1(83.28,142.8)
UB921_DIN11: length 80.5
  TOP w0.178: U11.28 v1(84.28,141.79) ; U8.38 v1(34.49,159.2)
  L03_SIG1 w0.107: v1(34.49,159.2) 34.99,158.71 44.86,158.71 46.88,156.68 54.45,156.68 54.56,156.57 54.56,153.02 54.19,152.65 50.72,152.65 50.62,152.56 50.62,152.43 50.72,152.33 53.81,152.33 53.9,152.24 53.9,152.11 53.81,152.01 50.4,152.01 50.3,152.11 50.3,152.56 50.21,152.65 49.8,152.65 49.69,152.55 49.69,151.9 51.16,150.43 51.72,150.43 53.9,148.25 53.9,146.71 54.98,145.64 56.77,145.64 58.81,143.6 75.76,143.6 76.25,143.11 77.85,143.11 78.34,143.6 82.24,143.6 82.78,143.06 82.78,142.07 83.06,141.79 v1(84.28,141.79)
UB921_DIN12: length 80.5
  TOP w0.178: v1(35.76,160.2) 35.26,159.7 U8.39 ; U12.3 v1(87.22,142.8)
  L03_SIG1 w0.107: v1(35.76,160.2) 36.1,160.2 36.58,159.72 45.31,159.72 47.43,157.61 55.05,157.61 55.62,157.03 55.62,151.66 54.38,150.42 53.58,150.42 53.47,150.32 53.47,149.99 54.83,148.64 54.83,147.46 55.01,147.28 55.23,147.28 55.33,147.38 55.33,147.83 55.54,148.04 56.13,148.04 56.24,147.93 56.24,147.7 56.14,147.6 55.74,147.6 55.65,147.51 55.65,147.38 55.74,147.28 56.61,147.28 56.9,146.99 56.9,146.72 57.01,146.62 57.39,146.62 57.5,146.74 58.03,146.74 59.59,145.18 59.59,144.72 59.7,144.61 85.14,144.61 85.25,144.5 85.25,144.22 85.34,144.13 86.43,144.13 86.53,144.04 86.53,143.12 86.43,143.02 86.3,143.02 86.21,143.12 86.21,143.72 86.11,143.81 85.98,143.81 85.89,143.72 85.89,143.12 85.79,143.02 85.66,143.02 85.57,143.12 85.57,143.72 85.47,143.81 85.34,143.81 85.25,143.72 85.25,142.8 85.44,142.61 87.02,142.61 v1(87.22,142.8)
UB921_DIN13: length 80.6
  TOP w0.178: U12.5 v1(88.22,142.3) ; U8.40 v1(34.49,160.2)
  L03_SIG1 w0.107: v1(34.49,160.2) 34.99,159.7 35.94,159.7 36.27,159.37 45.21,159.37 47.28,157.3 54.92,157.3 55.31,156.91 55.31,151.79 54.25,150.73 53.14,150.73 53.04,150.63 53.04,150 54.52,148.51 54.52,146.97 55.23,146.26 55.38,146.26 55.47,146.36 55.47,146.87 55.58,146.97 56.48,146.97 56.59,146.87 56.59,146.68 56.5,146.58 55.96,146.58 55.87,146.49 55.87,146.36 55.96,146.26 57.47,146.26 57.63,146.43 57.9,146.43 59.23,145.09 59.23,144.82 59.14,144.73 59.01,144.73 57.76,145.97 57.63,145.97 57.54,145.88 57.54,145.75 59,144.28 84.68,144.28 84.94,144.03 84.94,142.55 85.2,142.3 v1(88.22,142.3)
UB921_DIN14: length 80.6
  TOP w0.178: U8.41 35.26,160.7 v1(35.76,161.2) ; U12.7 v1(89.22,142.8)
  L03_SIG1 w0.107: v1(89.22,142.8) 88.8,142.8 88.14,143.46 88.14,143.92 87.66,144.41 87.2,144.41 86.33,145.27 60.91,145.27 60.8,145.38 60.8,146.01 59.13,147.69 58.34,147.69 58.08,147.44 57.34,147.44 56.95,147.82 56.95,148.37 56.66,148.66 55.69,148.66 54.77,149.58 54.77,149.93 55.32,150.48 55.54,150.48 55.63,150.38 55.63,149.29 55.72,149.2 56.55,149.2 56.64,149.29 56.64,149.42 56.55,149.52 56.04,149.52 55.95,149.61 55.95,149.74 56.04,149.84 56.55,149.84 56.64,149.93 56.64,150.06 56.55,150.16 56.04,150.16 55.95,150.25 55.95,150.38 56.04,150.48 56.64,150.48 56.95,150.78 56.95,151.24 56.24,151.94 56.24,152.62 57.66,154.03 57.66,155.88 55.3,158.23 47.77,158.23 45.62,160.38 45.57,160.38 45.52,160.43 36.88,160.43 36.11,161.2 v1(35.76,161.2)
UB921_DIN15: length 80.5
  TOP w0.178: U8.42 v1(34.49,161.2) ; U12.10 v1(90.72,142.8)
  L03_SIG1 w0.107: v1(90.72,142.8) 90.19,142.27 88.89,142.27 86.22,144.94 60.26,144.94 58.44,146.77 58.44,146.9 58.53,146.99 58.66,146.99 60.27,145.39 60.4,145.39 60.49,145.48 60.49,145.62 58.73,147.38 58.46,147.38 58.21,147.13 57.21,147.13 56.64,147.69 56.64,148.24 56.54,148.35 55.56,148.35 54.46,149.45 54.46,150.06 55.93,151.53 55.93,154.39 56.64,155.1 56.64,156.46 55.17,157.92 47.57,157.92 45.44,160.05 36.78,160.05 36.13,160.7 34.99,160.7 v1(34.49,161.2)
UB921_DIN16: length 80.4
  TOP w0.178: U8.25 v1(27.44,157.15) ; U12.12 v1(91.72,139.53)
  L03_SIG1 w0.107: v1(27.44,157.15) 27.52,157.15 27.93,156.73 27.93,153.12 31.34,149.72 44.73,149.72 56.72,137.73 57.09,137.73 57.18,137.82 57.18,138.48 57.29,138.59 57.86,138.59 57.98,138.46 57.98,138.31 57.86,138.18 57.71,138.18 57.61,138.08 57.61,137.83 57.71,137.73 60.76,137.73 62.33,139.3 76.1,139.3 77.56,137.84 84.9,137.84 86.36,139.3 91.49,139.3 v1(91.72,139.53)
UB921_DIN17: length 80.6
  TOP w0.178: v1(27.44,156.13) 27.94,156.63 U8.26 ; U12.14 v1(92.72,139.53)
  L03_SIG1 w0.107: v1(27.44,156.13) 27.44,153.13 31.19,149.39 44.55,149.39 51.28,142.65 51.28,141.74 52.54,140.48 53.17,140.48 56.29,137.37 60.91,137.37 62.48,138.95 75.98,138.95 77.41,137.52 85.04,137.52 86.46,138.95 92.14,138.95 v1(92.72,139.53)
UB921_DIN18: length 80.5
  TOP w0.178: U8.27 v1(28.44,157.15) ; U12.16 v1(93.72,141.79)
  L03_SIG1 w0.107: v1(93.72,141.79) 92.81,141.79 90.98,139.96 83.69,139.96 82.78,139.05 78.36,139.05 77.44,139.96 55.42,139.96 45.01,150.38 31.7,150.38 29.82,152.26 29.82,155.51 28.95,156.38 28.95,158.19 28.84,158.3 28.45,158.3 28.35,158.19 28.35,157.25 v1(28.44,157.15)
UB921_DIN19: length 80.6
  TOP w0.178: U8.28 28.94,156.63 v1(28.44,156.13) ; U12.20 v1(95.72,141.79)
  L03_SIG1 w0.107: v1(28.44,156.13) 29.31,155.27 29.31,152.31 31.57,150.05 44.86,150.05 55.27,139.63 77.33,139.63 78.23,138.73 83.19,138.73 84.09,139.63 91.11,139.63 92.68,141.21 95.14,141.21 v1(95.72,141.79)
UB921_DIN20: length 80.5
  TOP w0.178: U8.29 v1(29.44,157.15) ; U12.22 v1(96.72,141.79)
  L03_SIG1 w0.107: v1(29.44,157.15) 30.18,157.15 30.28,157.05 30.28,152.28 31.85,150.71 45.14,150.71 55.55,140.29 90.86,140.29 93.43,142.87 95.64,142.87 v1(96.72,141.79)
UB921_DIN21: length 80.5
  TOP w0.178: U12.24 v1(97.72,141.79) ; U8.32 v1(30.94,157.15)
  L03_SIG1 w0.107: v1(30.94,157.15) 31.09,157.01 31.09,156.17 30.63,155.71 30.63,153.32 32.94,151.02 41.94,151.02 42.6,151.67 45.67,151.67 56.69,140.65 90.73,140.65 93.28,143.2 96.31,143.2 v1(97.72,141.79)
UB921_DIN22: length 80.6
  TOP w0.178: U12.26 v1(98.72,142.8) ; v1(31.94,156.13) 31.44,156.63 U8.33
  L03_SIG1 w0.107: v1(31.94,156.13) 31.94,154.75 32.61,154.08 32.61,152.66 33.68,151.6 42.06,151.6 42.47,152 45.82,152 56.85,140.98 90.6,140.98 93.15,143.53 97.99,143.53 v1(98.72,142.8)
UB921_DIN23: length 80.5
  TOP w0.178: U12.28 v1(99.72,142.8) ; U8.34 v1(31.94,157.15)
  L03_SIG1 w0.107: v1(99.72,142.8) 98.66,143.86 93.03,143.86 90.47,141.31 58.65,141.31 56.08,143.87 54.46,143.87 45.97,152.36 42.32,152.36 41.91,151.95 34.7,151.95 33.73,152.92 33.73,154.03 32.45,155.32 32.45,156.65 v1(31.94,157.15)
UB921_FSEL: length 5.5
  TOP w0.178: R30.1 v1(24.31,165.5) 24.92,164.9 24.92,163.48 25.2,163.2 U8.15
  BOTTOM w0.178: R30.1 v1(24.31,165.5)
UB921_IDX: length 7.3
  TOP w0.178: U8.6 30.44,166.9 30.91,167.37 33.15,167.37 33.59,167.81 R24.1 R20.2
UB921_INTB: length 41.8
  TOP w0.178: R66.2 v1(34.37,153.42)
  L03_SIG1 w0.107: v1(69.79,156.41) 69.79,156.79 68.07,158.5 63.86,158.5 62.99,159.37 61.21,159.37 v1(60.66,158.81)
  BOTTOM w0.178: v1(60.66,158.81) 58.37,156.52 47.52,156.52 43.15,152.15 35.63,152.15 v1(34.37,153.42) ; U43.15 v1(69.79,156.41)
UB921_INTB_R: length 5.9
  TOP w0.178: R66.1 R65.1 R64.2 30.44,156.65 U8.31
UB921_MODE_SEL: length 4.6
  TOP w0.178: U8.24 26.69,155.4 R62.2 26.76,154.19 R70.1
UB921_REM_INTB: length 1.9
  TOP w0.178: U8.16 v1(25.77,162.7)
  BOTTOM w0.178: U8.16 v1(25.77,162.7)
UB921_RESETN: length 56.3
  TOP w0.178: U8.21 v1(25.65,160.2) 24.77,159.32 R55.2
  L03_SIG1 w0.107: v1(60.6,159.67) 60.71,159.77 63.2,159.77 64.11,158.86 68.37,158.86 v1(69.79,157.44)
  BOTTOM w0.178: v1(60.6,159.67) 57.89,156.95 47.37,156.95 42.95,152.54 36.49,152.54 34.07,154.95 34.07,157.26 32.88,158.45 27.4,158.45 v1(25.65,160.2) ; v1(69.79,157.44) 69.76,157.41 U43.13
UB926_CMLOUTN: length 2.3
  TOP w0.178: U2.53 v1(19.33,180.23)
  BOTTOM w0.178: v1(19.33,180.23) 19.33,180.69 19.51,180.87 TP21.1
UB926_CMLOUTP: length 5.3
  TOP w0.178: v1(18.39,180.23) 18.89,180.73 U2.52
  BOTTOM w0.178: TP23.1 18.57,178.73 18.39,178.91 v1(18.39,180.23)
UB926_DE: length 1.9
  TOP w0.178: v1(23.6,174.91) 23.58,174.93 U2.6
  BOTTOM w0.178: U2.6 23.58,174.93 v1(23.6,174.91)
UB926_GPIO1: length 160.2
  TOP w0.178: J1.30 v1(89.62,101.51)
  L08_SIG2 w0.107: v1(29.44,185.07) 29.44,187.37 28.93,187.88 25.87,187.88 25.58,188.17 18.05,188.17 16.66,186.79 16.66,173.9 15.29,172.53 15.29,163.96 18.04,161.21 18.04,159.95 19.58,158.4 19.58,150.74 24.27,146.06 34.54,146.06 41.15,139.45 42.56,139.45 42.91,139.1 42.91,138.1 48.86,132.15 48.86,128.38 55.95,121.28 58.95,121.28 60.17,120.06 v1(60.17,119.11)
  BOTTOM w0.178: v1(89.62,101.51) 87.45,103.68 87.45,109.62 88.05,110.22 88.05,114.16 86.25,115.96 79.69,115.96 76.62,112.88 72.25,112.88 69.77,115.36 63.4,115.36 60.17,118.59 v1(60.17,119.11) ; R535.1 29.41,185.1 v1(29.44,185.07)
UB926_GPIO2: length 149.6
  TOP w0.178: v1(86.5,117.37) 86.5,117.78 86.27,118.01 J1.75 ; U2.28 v1(31.24,182.73)
  L08_SIG2 w0.107: v1(31.24,182.73) 31.09,182.73 28.97,184.86 28.97,187.16 28.59,187.54 25.63,187.54 25.43,187.73 20.68,187.73 17.12,184.17 17.12,173.88 15.7,172.46 15.7,164.15 18.36,161.49 18.36,160.26 19.9,158.72 19.9,150.94 24.35,146.49 29.77,146.49 31.47,148.19 37.95,148.19 39.17,146.97 39.17,143.09 42.43,139.82 42.74,139.82 43.28,139.28 43.28,138.21 49.23,132.27 49.23,128.48 56.05,121.66 59.05,121.66 60.58,120.14 60.58,119.59 61.11,119.06 v1(62.08,119.06)
  BOTTOM w0.178: v1(62.08,119.06) 62.08,118.11 63.91,116.28 70.15,116.28 72.63,113.8 76.24,113.8 79.51,117.08 84.56,117.08 84.85,117.37 v1(86.5,117.37)
UB926_GPIO3: length 146
  TOP w0.178: v1(81.92,116.52) 82.42,117.03 82.42,118.18 83.25,119.01 J1.79 ; U2.27 v1(29.83,182.23)
  L08_SIG2 w0.107: v1(61.13,119.92) 61.13,120.35 61.32,120.54 61.32,121.22 60.5,122.03 56.18,122.03 49.58,128.63 49.58,132.42 43.73,138.27 43.73,139.29 42.81,140.2 42.58,140.2 39.71,143.07 39.71,147.16 38.27,148.61 31.32,148.61 29.51,146.81 24.52,146.81 21.17,150.16 21.17,157.93 18.85,160.26 18.85,161.61 16.1,164.36 16.1,172.39 17.49,173.77 17.49,184.06 20.82,187.38 24.88,187.38 25.22,187.04 27.88,187.04 28.38,186.54 28.38,183.68 v1(29.83,182.23)
  BOTTOM w0.178: v1(81.92,116.52) 79.59,116.52 76.42,113.35 72.45,113.35 69.97,115.83 63.51,115.83 61.13,118.21 v1(61.13,119.92)
UB926_GPIO_SPARE: length 99.3
  TOP w0.178: U15.7 57.4,132.13 57.14,132.39 v1(57.14,134.6)
  L03_SIG1 w0.107: v1(31.43,186.41) 31.43,186.84 31.29,186.98 25.37,186.98 24.9,186.51 24.9,184.55 24.18,183.83 22.03,183.83 21.35,183.14 21.35,177.48 23.34,175.48 23.83,175.48 24.1,175.2 24.1,172.69 25.93,170.86 25.93,167.45 25.06,166.57 25.06,159.29 26.14,158.21 26.14,146.76 27.28,145.61 27.28,142.02 26.66,141.4 26.66,138.97 29.41,136.22 48.92,136.22 51.04,134.09 56.63,134.09 v1(57.14,134.6)
  BOTTOM w0.178: R534.1 TP108.1 31.06,186.77 v1(31.43,186.41)
UB926_HS: length 2.8
  TOP w0.178: v1(24.74,174.91) 24.58,175.07 U2.8
  BOTTOM w0.178: TP28.1 25.76,175.22 25.45,174.91 v1(24.74,174.91)
UB926_I2S_CLK: length 84.4
  TOP w0.178: U17.6 v1(66.81,120.15) ; v1(18.08,174.1) 18.09,174.09 R18.1
  L08_SIG2 w0.107: v1(18.08,174.1) 18.08,173.77 19.59,172.26 19.59,163.14 24.56,158.17 24.56,153.68 28.12,150.12 38.86,150.12 43.18,145.8 43.18,140.37 48.67,134.88 48.67,134.65 63.17,120.15 v1(66.81,120.15)
UB926_I2S_DA: length 99.3
  TOP w0.178: U17.3 68.76,119.88 v1(68.83,119.81) ; U2.45 v1(21.08,185.48)
  L08_SIG2 w0.107: v1(68.83,119.81) 68.01,120.63 64.11,120.63 56.18,128.56 55.22,128.56 49,134.78 49,135.01 43.51,140.5 43.51,145.93 38.91,150.53 28.4,150.53 24.92,154.01 24.92,158.25 19.9,163.27 19.9,172.43 18.82,173.52 18.82,174.96 19.89,176.03 19.89,185.15 20.22,185.48 v1(21.08,185.48)
UB926_I2S_DB: length 101.2
  TOP w0.178: U2.18 v1(29.83,177.73) ; v1(68.52,117.22) 68.11,116.81 U17.13
  L08_SIG2 w0.107: v1(20.07,174.43) 20.52,173.97 20.52,163.54 26.22,157.84 26.22,153.82 28.85,151.19 39.47,151.19 44.22,146.44 44.22,140.75 48.72,136.25 49.4,136.25 62.71,122.94 66.88,122.94 69.93,119.9 69.93,118.63 v1(68.52,117.22)
  BOTTOM w0.178: v1(29.83,177.73) 28.92,176.82 22.45,176.82 v1(20.07,174.43)
UB926_I2S_WC: length 111.3
  TOP w0.178: v1(28.85,184.25) 28.85,184.24 28.93,184.16 U2.30 ; v1(66.09,117.18) 66.16,117.11 U17.10
  L08_SIG2 w0.107: v1(66.09,117.18) 66.67,117.76 68.61,117.76 69.6,118.75 69.6,119.74 68.35,120.99 64.21,120.99 49.3,135.9 48.56,135.9 43.84,140.62 43.84,146.24 39.23,150.85 28.71,150.85 25.88,153.68 25.88,157.72 20.21,163.39 20.21,172.61 19.28,173.54 19.28,174.81 20.42,175.95 v1(20.42,184.74)
  BOTTOM w0.178: v1(28.85,184.25) 28.66,184.07 21.09,184.07 v1(20.42,184.74)
UB926_IDX: length 8.1
  TOP w0.178: U2.56 18.78,178.73 17.78,177.73 R14.1 R13.2
UB926_INTN: length 1.8
  TOP w0.178: U2.16 R15.1
UB926_LOCK: length 83.2
  TOP w0.178: U2.32 v1(27.58,185.48) ; v1(56.18,134.68) 56.18,132.49 57.04,131.63 U15.8
  L03_SIG1 w0.107: v1(27.58,185.48) 27.94,185.12 27.94,176.64 27.58,176.28 27.58,172.07 26.57,171.06 26.57,150.93 27.13,150.37 27.13,147.62 27.13,147.62 27.13,146.87 28.04,145.96 29.57,145.96 30.43,145.09 30.43,138.2 32.11,136.53 49.1,136.53 51.19,134.44 55.94,134.44 v1(56.18,134.68)
UB926_MCLK: length 2.4
  TOP w0.178: v1(19.05,175.98) 19.8,176.73 U2.60
  BOTTOM w0.178: TP27.1 v1(19.05,175.98)
UB926_PASS: length 3.7
  TOP w0.178: U2.42 22.58,185.28 v1(22.12,185.73)
  BOTTOM w0.178: v1(22.12,185.73) 21.09,186.77 TP19.1
UB926_PCLK: length 2.8
  TOP w0.178: U2.5 23.08,174.67 23.34,174.4 23.84,174.4 24.02,174.23 R19.2
UB926_RESETN: length 85.2
  TOP w0.178: v1(19.02,176.87) 19.39,177.23 U2.59 ; v1(59.28,134.69) 59.78,134.2 U15.4
  L03_SIG1 w0.107: v1(19.02,176.87) 19.66,176.87 20.57,175.95 20.57,171.71 21.49,170.8 21.49,169.58 23.27,167.8 23.27,155.29 22.52,154.54 22.52,148.11 24.59,146.03 24.59,136.03 25.3,135.31 43.31,135.31 44.04,134.58 46.28,134.58 47.5,133.36 57.95,133.36 v1(59.28,134.69)
  BOTTOM w0.178: v1(19.02,176.87) 19.26,177.1 R329.1
UB926_ROUT13: length 2.9
  TOP w0.178: U2.22 29.76,179.73 v1(30.18,179.31)
  BOTTOM w0.178: U2.22 29.76,179.73 v1(30.18,179.31)
UB926_TUNER_RESET: length 89.9
  TOP w0.178: v1(58.27,134.69) 58.78,134.18 U15.6 ; R4.2 22.8,185.76 v1(23.08,185.48) U2.41
  L03_SIG1 w0.107: v1(23.08,185.48) 20.93,183.33 20.93,177.25 23.04,175.14 23.04,172.65 22.81,172.42 22.81,171 23.58,170.23 23.58,157.48 24.74,156.32 24.74,146.33 25.76,145.31 25.76,138.35 28.33,135.77 45.6,135.77 47.66,133.71 57.29,133.71 v1(58.27,134.69)
UB926_VS: length 4.7
  TOP w0.178: v1(25.91,174.48) 25.78,174.35 24.59,174.35 24.13,174.81 24.13,175.83 U2.7
  BOTTOM w0.178: v1(25.91,174.48) 26.01,174.38 TP30.1
V_DVDD: length 12.5
  TOP w0.381: C34.1 v1(82.91,164.87) ; v1(79.97,157.49) 79.97,157.53 80.35,157.91 R59.1 ; C33.1 v1(96.62,166.87)
  BOTTOM w0.254: 84.09,159.13 U41.1 ; C33.1 v1(96.62,166.87) ; C34.1 v1(82.91,164.87)
  BOTTOM w0.381: FL22.1 C243.1 v1(80.57,168.58) ; 84.09,159.13 84.09,158.69 83.29,157.89 C256.1 v1(81.76,157.89) ; v1(79.97,157.49) 79.97,157.25 80.29,156.93 R346.2
V_PVDD: length 7.8
  BOTTOM w0.203: U41.18 86.54,169.8
  BOTTOM w0.381: 86.54,169.8 85.94,170.39 C237.1 C238.1 C235.1 FL20.1
V_TVDD: length 10.7
  TOP w0.381: C30.1 v1(89.04,170.17) ; C31.1 v1(92.04,170.17) ; v1(87.38,171.05) 87.86,170.57 R21.1
  BOTTOM w0.254: C30.1 v1(89.04,170.17) ; C31.1 v1(92.04,170.17)
  BOTTOM w0.381: FL21.1 C242.1 v1(83.8,169.96)
VCOMAD1: length 71.1
  TOP w0.381: 34.88,51.65 C159.1 36.46,51.17 v1(35.94,50.66) ; 34.88,51.65 34.23,51 U29.3 ; 34.88,51.65 U29.5 ; v1(24.6,58.44) C152.1 23.11,57.45 ; U28.5 23.11,57.45 23.11,57.45 ; R230.1 C774.1 v1(16.46,61.58) ; 23.11,57.45 22.46,56.79 U28.3 ; 34.88,62.25 34.23,61.6 U27.3 ; 34.88,62.25 C145.1 36.46,61.91 v1(35.97,61.43) ; 34.88,62.25 U27.5 ; v1(16.46,53.32) C773.1 R239.1
  BOTTOM w0.381: 34.88,51.25 U55.5 ; 34.88,51.25 34.23,51.9 U55.3 ; 34.88,51.25 35.28,51.65 C159.1 36.46,50.98 v1(36.83,50.61) ; U53.3 34.23,62.44 34.88,61.79 ; U51.3 17.43,75.1 18.08,74.45 ; v1(36.86,61.43) 36.46,61.83 C145.1 35.35,62.25 34.88,61.79 ; 34.88,61.79 U53.5 ; v1(19.65,73.76) C330.1 18.08,74.45 ; v1(15.78,54.1) C773.1 R239.1 ; v1(24.6,56.46) C152.1 23.68,57.45 23.11,56.87 ; 29.3,72.42 28.82,71.94 C139.1 v1(26.49,71.24) ; 29.3,72.42 29.31,72.43 U26.3 ; 29.3,72.42 29.96,71.77 U26.5 ; U179.1 39.5,47.61 v1(39.76,47.87) 40.15,47.48 U179.2 ; 18.08,74.45 U51.5 ; R230.1 C774.1 v1(15.78,60.79) ; 23.11,56.87 U54.5 ; 23.11,56.87 22.46,57.52 U54.3
VCOMAD1_CODEC: length 14.7
  TOP w0.254: U32.1 46.64,49.24
  TOP w0.381: 46.64,49.24 46.64,50.67 46.06,51.25 C171.1
  BOTTOM w0.381: v1(43.23,50.66) 41.95,50.66 40.8,49.51 U179.3 40.8,44.6 41.45,43.95 U179.5
  vias: v1(43.19,51.55) v1(44.08,51.56) v1(44.1,50.65)
VCOMAD1_SPARE: length 5.2
  BOTTOM w0.178: U179.7 40.15,42.99 40.33,43.17 40.62,43.17 40.8,42.99 U179.6 40.8,40.07 TP171.1
VCOMAD2: length 70.7
  TOP w0.381: 23.11,90.37 C113.1 v1(24.6,91.41) ; 23.11,90.37 23.11,90.38 U22.5 ; 23.11,90.37 22.46,89.72 U22.3 ; v1(36.02,97.11) 36.46,96.67 C103.1 34.88,96.17 ; U52.3 16.78,74.99 16.14,74.35 ; 34.88,96.17 U20.5 ; 34.88,96.17 34.23,95.52 U20.3 ; v1(35.94,86.55) 36.46,86.03 C119.1 34.88,85.57 ; 27.84,72.55 27.84,72.17 28.01,72 U24.5 ; 27.84,72.55 C336.1 v1(26.49,74.15) ; 27.84,72.55 28.66,73.37 U24.3 ; 16.14,74.35 15.58,74.35 14.99,74.95 C124.1 v1(14.61,74.21) ; 16.14,74.35 16.13,74.34 U52.5 ; v1(16.46,94.5) C768.1 R182.1 ; R192.1 C767.1 v1(16.46,86.24) ; U23.5 34.88,85.57 ; 34.88,85.57 34.23,84.92 U23.3
  BOTTOM w0.381: v1(36.91,86.57) 36.46,86.12 C119.1 34.88,85.57 ; 34.88,85.57 34.23,86.22 U50.3 ; 34.88,85.57 U50.5 ; 34.88,96.17 34.23,96.82 U48.3 ; 34.88,96.17 U48.5 ; 34.88,96.17 C103.1 36.46,96.66 v1(36.91,97.11) ; v1(15.78,93.72) C768.1 R182.1 ; v1(24.6,89.4) C113.1 23.11,90.37 ; U180.2 57.34,94.59 v1(56.98,94.24) 56.69,94.53 U180.1 ; v1(15.78,87.03) C767.1 R192.1 ; 23.11,90.37 22.46,91.02 U49.3 ; 23.11,90.37 U49.5
VCOMAD2_CODEC: length 11.6
  TOP w0.305: U19.1 58.04,99.32 C100.1
  TOP w0.381: C100.1 58.07,98.59 v1(57.71,98.23)
  BOTTOM w0.381: v1(57.71,97.34) 57.99,97.06 U180.3 57.99,94.52 58.64,93.87 U180.5
  vias: v1(58.73,98.23) v1(58.73,97.34)
VCOMAD2_SPARE: length 5.2
  BOTTOM w0.178: TP172.1 58.4,89.94 57.99,90.35 U180.6 57.99,92.38 57.78,92.59 57.48,92.59 57.34,92.45 U180.7
VCOMDA1: length 4.3
  TOP w0.254: U32.15 45.77,41.43 45.52,41.18 45.52,39.23 45.12,38.83 C193.1
VCOMDA2: length 4
  TOP w0.254: C74.1 59.77,111.09 59.07,110.39 U19.15
VLDO_CAM_1V8: length 1.5
  TOP w0.254: U1.5 60.9,194.45 60.57,194.79 R2.1
VLDO_CAM_3V3: length 1.5
  TOP w0.254: R3.1 60.57,193.62 60.9,193.95 U1.6
VOUT0_DATA0: length 63.6
  TOP w0.178: J1.39 83.41,104.01 83.16,103.75 83.16,102.62 82.98,102.45 81.73,102.45 81.58,102.6 81.58,103.87 81.42,104.02 81.2,104.02 81.04,103.87 81.04,102.6 80.89,102.45 80.67,102.45 80.51,102.6 80.51,103.87 80.35,104.02 80.13,104.02 79.98,103.87 79.98,102.6 79.82,102.45 79.6,102.45 79.44,102.6 79.44,103.87 79.29,104.02 79.07,104.02 78.91,103.87 78.91,102.6 78.75,102.45 78.44,102.45 78.11,102.78 78.11,104.66 78.26,104.82 79.6,104.82 79.76,104.97 79.76,105.2 79.6,105.35 78.26,105.35 78.11,105.51 78.11,107.93 78.98,108.81 v1(78.98,128.93) ; U11.2 71.28,139.73 72.34,138.67 72.34,137.24 73.28,136.31 v1(73.28,136.3)
  BOTTOM w0.178: v1(78.98,128.93) 78.98,128.81 78.7,128.53 76.07,128.53 75.79,128.81 75.79,133.97 73.46,136.3 v1(73.28,136.3)
